Omron CX-Programmer project NewProject (CX-Programmer 8.10)

# PLC NewPLC1: CJ1M CPU11
I/O table (CPU CJ1M-CPU11): rack 0 slot 0 CJ1W-ETN21(ETN21Mode); rack 0 slot 1 CJ1W-ID211; rack 0 slot 2 CJ1W-OC211

## Global symbols (name address type ; comment)
T0000 BOOL  ; Bar Code Read Completion Bit From ProFace Screen Reset Timer
W0.00 BOOL  ; Bar Code Read Completion Bit From ProFace Screen
W1.00 BOOL  ; Bar Code Read Completion Bit From ProFace Screen Latch
W2.00 BOOL  ; Bar Code Read Completion Bit To ProFace Screen Reset
W3.00 BOOL  ; Reset Scanner
BarCodeScanCompareWord D300 STRING[20]  ; Bar Code Scan Compare Word
BarCodeScanStorageWord D200 STRING[20]  ; Bar Code Scan Storage Word
BarCodeScanWord D100 STRING[20]  ; Bar Code Scan Word
Spaces D50 STRING[20]  ; Spaces

## Program NewProgram1 (cyclic task 0)

### Section Section1

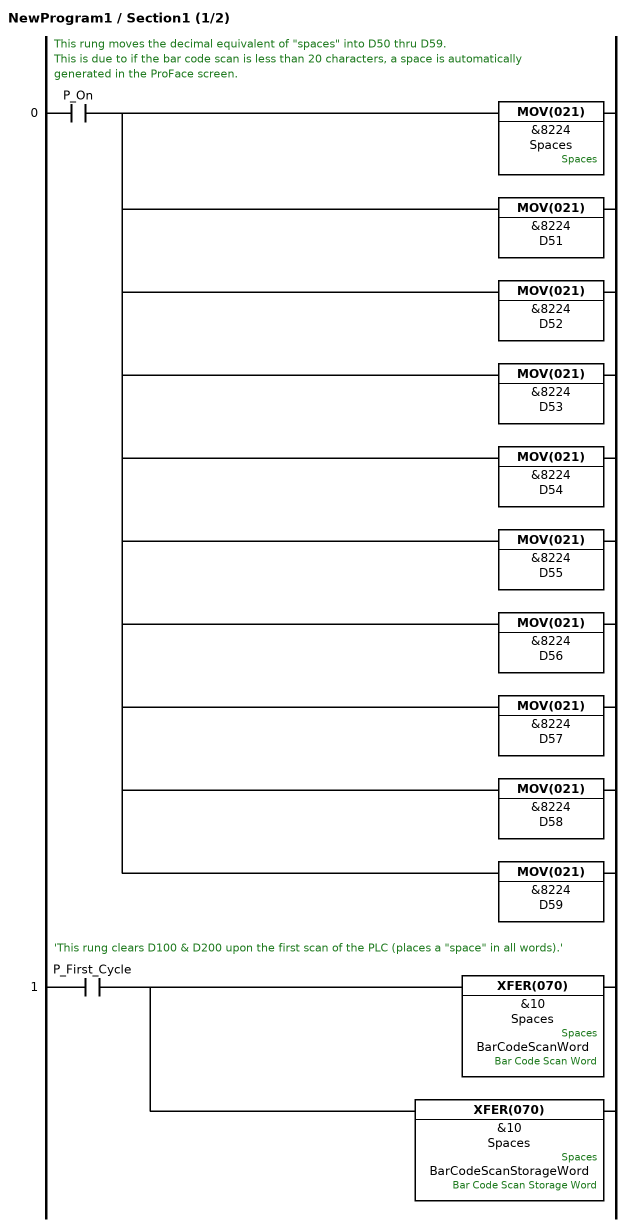
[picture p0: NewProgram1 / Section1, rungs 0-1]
; rung 0: This rung moves the decimal equivalent of "spaces" into D50 thru D59. / This is due to if the bar code scan is less than 20 characters, a space is automatically generated in the ProFace screen.
LD P_On
MOV(021) &8224 Spaces  ; Spaces
MOV(021) &8224 D51
MOV(021) &8224 D52
MOV(021) &8224 D53
MOV(021) &8224 D54
MOV(021) &8224 D55
MOV(021) &8224 D56
MOV(021) &8224 D57
MOV(021) &8224 D58
MOV(021) &8224 D59
; rung 1: 'This rung clears D100 & D200 upon the first scan of the PLC (places a "space" in all words).'
LD P_First_Cycle
XFER(070) &10 Spaces BarCodeScanWord  ; Spaces, Bar Code Scan Word
XFER(070) &10 Spaces BarCodeScanStorageWord  ; Spaces, Bar Code Scan Storage Word

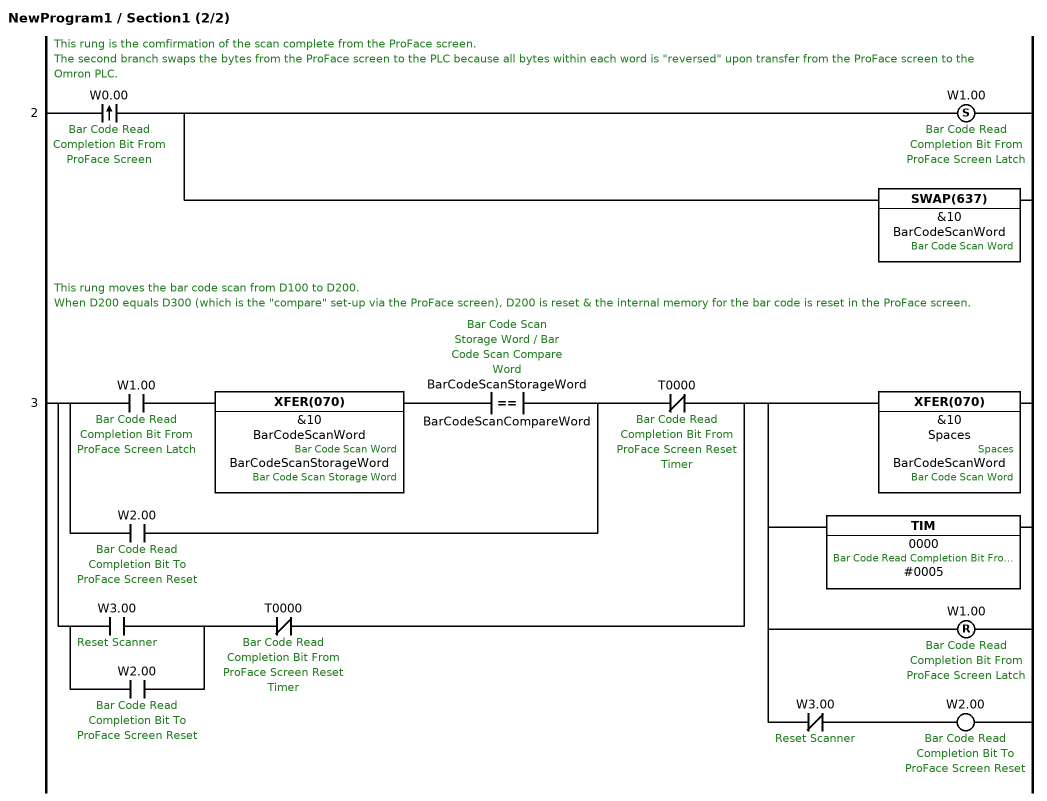
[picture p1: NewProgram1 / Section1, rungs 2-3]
; rung 2: This rung is the comfirmation of the scan complete from the ProFace screen. / The second branch swaps the bytes from the ProFace screen to the PLC because all bytes within each word is "reversed" upon transfer from the ProFace screen to the Omron PLC.
@LD W0.00  ; Bar Code Read Completion Bit From ProFace Screen
SET W1.00  ; Bar Code Read Completion Bit From ProFace Screen Latch
SWAP(637) &10 BarCodeScanWord  ; Bar Code Scan Word
; rung 3: This rung moves the bar code scan from D100 to D200. / When D200 equals D300 (which is the "compare" set-up via the ProFace screen), D200 is reset & the internal memory for the bar code is reset in the ProFace screen.
LD W1.00  ; Bar Code Read Completion Bit From ProFace Screen Latch
XFER(070) &10 BarCodeScanWord BarCodeScanStorageWord  ; Bar Code Scan Word, Bar Code Scan Storage Word
AND=$(670) BarCodeScanStorageWord BarCodeScanCompareWord  ; Bar Code Scan Storage Word, Bar Code Scan Compare Word
OR W2.00  ; Bar Code Read Completion Bit To ProFace Screen Reset
ANDNOT T0000  ; Bar Code Read Completion Bit From ProFace Screen Reset Timer
LD W3.00  ; Reset Scanner
OR W2.00  ; Bar Code Read Completion Bit To ProFace Screen Reset
ANDNOT T0000  ; Bar Code Read Completion Bit From ProFace Screen Reset Timer
ORLD
XFER(070) &10 Spaces BarCodeScanWord  ; Spaces, Bar Code Scan Word
TIM 0000 #0005  ; Bar Code Read Completion Bit From ProFace Screen Reset Timer
RSET W1.00  ; Bar Code Read Completion Bit From ProFace Screen Latch
ANDNOT W3.00  ; Reset Scanner
OUT W2.00  ; Bar Code Read Completion Bit To ProFace Screen Reset

### Section END
; rung 0
END(001)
